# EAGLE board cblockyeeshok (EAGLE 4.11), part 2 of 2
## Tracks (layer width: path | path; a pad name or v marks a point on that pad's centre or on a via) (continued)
N$164  (via drill 0.61) (continued)
  Top 0.203: v59.05,135.89 59.05,135.25 56.52,132.72 50.8,132.72 50.16,132.08 46.35,132.08 SIDE10.6
  Bottom 0.203: v59.05,135.89 60.96,133.99 A4.B1
N$165
  Top 0.203: SIDE10.8 46.35,129.54 60.33,129.54 60.96,128.91 A4.D1
N$166
  Top 0.203: SIDE10.12 46.35,124.46 56.52,124.46 57.15,123.83 63.5,123.83 64.14,124.46 A4.E1
N$167
  Top 0.203: SIDE10.14 46.35,121.92 52.7,121.92 53.98,123.19 60.33,123.19 60.96,122.56 A4.F1
N$168
  Top 0.203: SIDE10.16 46.35,119.38 56.52,119.38 57.15,120.02 63.5,120.02 64.14,119.38 A4.H1
N$169
  Top 0.203: SIDE10.20 46.35,114.3 49.53,114.3 52.07,116.84 58.42,116.84 59.69,115.57 60.96,115.57 A4.J1
N$170  (via drill 0.61)
  Top 0.203: v50.16,113.03 56.52,113.03 57.15,113.67 63.5,113.67 64.14,113.03 A4.K1
  Bottom 0.203: v50.16,113.03 46.35,116.84 SIDE10.18
N$171
  Top 0.203: SIDE10.24 46.35,109.22 47.62,109.22 48.9,110.49 60.33,110.49 60.96,109.86 A4.L1
N$172
  Top 0.203: SIDE10.28 46.35,104.14 59.05,104.14 61.59,106.68 64.14,106.68 A4.M1
N$173
  Bottom 0.203: A4.N1 60.96,103.5 57.15,103.5 50.16,110.49 47.62,110.49 46.35,111.76 SIDE10.22
N$174
  Top 0.203: SIDE10.30 46.35,101.6 52.7,101.6 56.52,97.79 62.87,97.79 64.14,99.06 A4.P1
N$175
  Bottom 0.203: SIDE10.26 46.35,106.68 53.34,106.68 60.96,99.06 60.96,97.16 A4.R1
N$176
  Top 0.203: SIDE10.32 46.35,99.06 50.16,99.06 57.15,92.08 63.5,92.08 64.14,92.71 A4.S1
N$177
  Top 0.203: SIDE10.34 46.35,96.52 51.44,96.52 57.15,90.81 60.96,90.81 A4.T1
N$178  (via drill 0.61)
  Top 0.203: v47.62,127 46.35,128.27 45.09,128.27 44.45,128.91 44.45,132.72 45.72,133.99 SIDE10.4
  Bottom 0.203: v47.62,127 50.8,123.83 55.24,123.83 62.87,116.2 62.87,92.71 64.14,91.44 64.14,87.63 A4.U1
N$179  (via drill 0.61)
  Top 0.203: v64.14,103.5 62.23,105.41 v61.59,105.41 | v59.69,116.84 v61.59,118.75
  Bottom 0.203: v64.14,103.5 69.22,98.42 69.22,88.9 64.14,83.82 61.59,83.82 A4.V1 | v61.59,105.41 61.59,106.68 59.69,108.58 v59.69,116.84 | v61.59,118.75 61.59,119.38 66.04,123.83 66.04,125.73 61.59,130.18 53.98,130.18 46.99,137.16 46.35,137.16 SIDE10.2
N$180  (via drill 0.61)
  Top 0.203: SIDE10.33 43.18,97.16 43.18,98.42 SIDE10.31 43.18,99.69 43.18,100.97 SIDE10.29 | SIDE10.27 43.18,104.78 43.18,106.05 SIDE10.25 43.18,107.31 43.18,108.58 SIDE10.23 43.18,109.86 40.64,109.86 v37.47,106.68 | SIDE10.21 43.18,112.39 43.18,113.67 SIDE10.19 43.18,114.94 43.18,116.2 SIDE10.17 43.18,117.47 43.18,118.75 SIDE10.15 | SIDE10.3 43.18,133.99 43.18,132.72 SIDE10.5 43.18,131.44 43.18,130.18 SIDE10.7 43.18,128.91 43.18,127.64 SIDE10.9 43.18,126.36 43.18,125.09 SIDE10.11 43.18,123.83 43.18,122.56 SIDE10.13 42.55,121.92 v41.27,120.65 | v40.64,134.62 40.64,135.25 42.55,137.16 SIDE10.1 | v59.69,132.08 64.14,132.08 A4.C1 | v34.92,111.76 v34.92,119.38
  Bottom 0.203: v37.47,106.68 42.55,101.6 SIDE10.29 | v40.64,134.62 42.55,134.62 SIDE10.3 | v59.69,132.08 53.34,138.43 45.09,138.43 43.81,137.16 SIDE10.1 | v41.27,120.65 42.55,119.38 SIDE10.15 | v34.92,111.76 42.55,104.14 SIDE10.27 | v34.92,119.38 40.64,119.38 SIDE10.17
N$181  (via drill 0.61)
  Top 0.203: SIDE11.33 137.16,13.34 137.16,14.61 SIDE11.31 137.16,15.88 137.16,17.14 SIDE11.29 | SIDE11.27 137.16,20.95 137.16,22.23 SIDE11.25 137.16,23.5 137.16,24.77 SIDE11.23 137.16,26.04 137.16,27.3 SIDE11.21 | SIDE11.19 137.16,31.11 137.16,32.38 SIDE11.17 137.16,33.66 137.16,34.92 SIDE11.15 137.16,36.2 137.16,37.47 SIDE11.13 137.16,38.73 137.16,40.01 SIDE11.11 137.16,41.27 137.16,42.55 SIDE11.9 | SIDE11.5 137.16,47.62 137.16,46.35 SIDE11.7 136.53,45.72 v135.25,44.45 | v138.43,55.24 137.16,53.98 SIDE11.1
  Bottom 0.203: SIDE11.27 137.16,19.68 137.16,18.41 SIDE11.29 | SIDE11.19 137.16,29.84 137.16,28.57 SIDE11.21 | SIDE11.5 137.16,48.9 137.16,50.16 SIDE11.3 137.16,51.44 137.16,52.7 SIDE11.1 | v138.43,55.24 134.62,59.05 134.62,68.58 121.28,81.92 97.16,81.92 96.52,81.28 94.61,81.28 85.72,72.39 85.72,67.94 83.82,66.04 83.82,62.23 A6.C2 | v135.25,44.45 136.53,43.18 SIDE11.9
N$182  (via drill 0.61)
  Top 0.203: v132.08,66.04 139.7,58.42 139.7,53.98 SIDE11.2 | v111.12,78.74 109.86,77.47 105.41,77.47 v104.78,78.11 | v102.87,76.2 102.87,74.3 99.69,71.12 96.52,71.12 v95.89,71.75 | v87.63,72.39 83.82,68.58 A6.A2
  Bottom 0.203: v132.08,66.04 119.38,78.74 v111.12,78.74 | v102.87,76.2 v104.78,78.11 | v95.89,71.75 94.61,71.75 93.34,73.03 88.27,73.03 v87.63,72.39
N$183  (via drill 0.61)
  Top 0.203: v132.08,48.9 135.25,52.07 137.79,52.07 139.06,50.8 SIDE11.4 | v121.92,49.53 116.84,54.61 111.12,54.61 v108.58,52.07
  Bottom 0.203: v132.08,48.9 128.27,48.9 127.64,49.53 v121.92,49.53 | v108.58,52.07 100.97,44.45 96.52,44.45 80.64,60.33 80.64,64.14 A6.B2
N$184  (via drill 0.61)
  Top 0.203: v90.17,66.04 83.19,59.05 80.64,59.05 A6.D2 | v95.25,66.04 97.16,66.04 102.87,71.75 v109.86,71.75
  Bottom 0.203: v90.17,66.04 v95.25,66.04 | v109.86,71.75 114.94,71.75 118.75,67.94 119.38,67.94 122.56,64.77 127.64,64.77 133.35,59.05 133.35,57.78 136.53,54.61 137.79,54.61 138.43,53.98 138.43,50.16 139.7,48.9 SIDE11.6
N$185  (via drill 0.61)
  Top 0.203: v83.82,58.42 83.82,55.88 A6.E2 | v129.54,72.39 130.18,72.39 144.15,58.42 v144.15,46.99
  Bottom 0.203: v83.82,58.42 83.82,59.69 85.09,60.96 85.09,66.67 86.36,67.94 86.36,72.39 94.61,80.64 96.52,80.64 97.16,81.28 120.65,81.28 v129.54,72.39 | v144.15,46.99 142.88,45.72 140.34,45.72 SIDE11.8
N$186  (via drill 0.61)
  Top 0.203: v138.43,31.75 138.43,41.27 139.7,42.55 SIDE11.10 | v135.89,31.75 135.89,30.48 121.92,16.51 v107.95,16.51
  Bottom 0.203: v135.89,31.75 v138.43,31.75 | v107.95,16.51 105.41,16.51 100.97,12.06 97.16,12.06 87,22.23 82.55,22.23 81.92,22.86 81.92,24.13 82.55,24.77 82.55,27.94 81.28,29.21 81.28,29.84 78.74,32.38 78.74,50.16 80.01,51.44 A6.F2
N$187  (via drill 0.61)
  Top 0.203: v85.09,28.57 85.09,25.4 89.53,20.95 89.53,20.32 101.6,8.26 128.27,8.26 v128.91,7.62 | v146.69,10.16 146.69,16.51 144.15,19.05 144.15,22.23 144.78,22.86 144.78,34.92 139.7,40.01 SIDE11.12
  Bottom 0.203: v85.09,28.57 85.09,43.18 83.82,44.45 83.82,48.26 A6.H2 | v128.91,7.62 131.44,7.62 132.08,8.26 135.89,8.26 136.53,7.62 144.15,7.62 v146.69,10.16
N$188  (via drill 0.61)
  Top 0.203: v80.01,29.84 81.92,31.75 81.92,33.66 81.28,34.29 81.28,36.83 81.92,37.47 81.92,40.01 80.64,41.27 80.64,45.09 A6.J2 | v140.97,16.51 140.97,36.2 139.7,37.47 SIDE11.14
  Bottom 0.203: v80.01,29.84 81.92,27.94 81.92,24.77 81.28,24.13 81.28,21.59 81.92,20.95 81.92,14.61 93.98,2.54 120.65,2.54 134.62,16.51 v140.97,16.51
N$189  (via drill 0.61)
  Top 0.203: v78.74,13.34 78.74,27.3 82.55,31.11 82.55,33.66 81.92,34.29 81.92,36.83 83.19,38.1 83.19,41.91 A6.K2 | v134.62,5.71 142.24,13.34 v142.24,33.66
  Bottom 0.203: v78.74,13.34 90.81,1.27 130.18,1.27 v134.62,5.71 | v142.24,33.66 140.34,35.56 SIDE11.16
N$190  (via drill 0.61)
  Top 0.203: v84.45,24.77 85.09,24.13 85.09,21.59 84.45,20.95 84.45,19.05 v87,16.51 | v128.27,11.43 v135.89,11.43
  Bottom 0.203: v84.45,24.77 84.45,26.67 81.92,29.21 81.92,33.66 80.64,34.92 80.64,38.73 A6.L2 | v87,16.51 95.25,8.26 120.02,8.26 122.56,5.71 v128.27,11.43 | v135.89,11.43 140.97,11.43 146.69,17.14 146.69,25.4 139.7,32.38 SIDE11.18
N$191  (via drill 0.61)
  Top 0.203: v88.27,23.5 88.27,27.3 83.82,31.75 83.82,35.56 A6.M2 | v97.79,14.61 98.42,15.24 123.83,15.24 128.91,20.32 v135.25,20.32
  Bottom 0.203: v88.27,23.5 88.27,22.86 96.52,14.61 v97.79,14.61 | v135.25,20.32 136.53,21.59 143.51,21.59 144.78,22.86 144.78,24.77 139.7,29.84 SIDE11.20
N$192  (via drill 0.61)
  Top 0.203: v120.65,49.53 108.58,49.53 106.05,52.07 106.05,53.98 103.5,56.52 101.6,56.52 100.97,55.88 100.97,53.34 104.14,50.16 104.14,48.26 103.5,47.62 92.71,47.62 91.44,46.35 91.44,45.72 89.53,43.81 85.72,43.81 82.55,46.99 79.38,46.99 78.74,46.35 78.74,38.73 80.01,37.47 80.01,33.66 A6.N2 | v133.99,27.3 135.89,29.21 137.79,29.21 139.06,27.94 SIDE11.22
  Bottom 0.203: v120.65,49.53 123.19,46.99 128.27,46.99 128.91,47.62 130.18,47.62 131.44,46.35 131.44,43.18 130.18,41.91 130.18,31.11 v133.99,27.3
N$193  (via drill 0.61)
  Top 0.203: v83.19,20.95 81.92,22.23 81.92,24.13 83.19,25.4 83.19,29.21 A6.P2 | v120.02,6.99 v122.56,6.99
  Bottom 0.203: v83.19,20.95 83.19,19.68 85.72,17.14 85.72,16.51 87,15.24 87.63,15.24 95.89,6.99 v120.02,6.99 | v122.56,6.99 122.56,8.26 130.18,15.88 130.18,16.51 135.89,22.23 135.89,23.5 136.53,24.13 137.79,24.13 139.06,25.4 SIDE11.24
N$194  (via drill 0.61)
  Top 0.203: v143.51,22.86 143.51,16.51 145.41,14.61 v145.41,12.7 | v136.53,9.53 131.44,4.45 101.6,4.45 96.52,9.53 v90.81,9.53 | v85.09,13.34 85.09,17.78 80.64,22.23 80.64,26.04 A6.R2
  Bottom 0.203: v143.51,22.86 140.34,22.86 SIDE11.26 | v145.41,12.7 142.24,9.53 v136.53,9.53 | v90.81,9.53 88.9,9.53 v85.09,13.34
N$195  (via drill 0.61)
  Top 0.203: v138.43,26.67 138.43,22.23 139.7,20.95 SIDE11.28 | v125.09,12.06 102.23,12.06 v100.97,13.34
  Bottom 0.203: v138.43,26.67 136.53,26.67 132.08,22.23 132.08,19.05 v125.09,12.06 | v100.97,13.34 100.33,12.7 97.79,12.7 87.63,22.86 83.82,22.86 A6.S2
N$196  (via drill 0.61)
  Top 0.203: v143.51,15.24 144.15,14.61 144.15,10.16 135.25,1.27 95.89,1.27 80.64,16.51 80.64,19.68 A6.T2
  Bottom 0.203: v143.51,15.24 140.97,17.78 140.34,17.78 SIDE11.30
N$197  (via drill 0.61)
  Top 0.203: v101.6,5.71 132.08,5.71 133.35,6.99 133.35,7.62 136.53,10.79 137.16,10.79 139.06,12.7 SIDE11.34
  Bottom 0.203: v101.6,5.71 100.33,5.71 97.79,3.17 93.98,3.17 83.82,13.34 83.82,16.51 A6.U2
N$198
  Bottom 0.203: A6.V2 80.64,13.34 81.92,13.34 93.34,1.91 120.65,1.91 132.72,13.97 137.79,13.97 139.06,15.24 SIDE11.32
N$199  (via drill 0.61)
  Top 0.203: v109.22,80.01 110.49,80.01 111.12,80.64 v123.83,80.64 | v153.67,46.99 153.67,45.09 152.4,43.81 SIDE12.10
  Bottom 0.203: v109.22,80.01 99.06,69.85 95.25,69.85 93.98,71.12 91.44,68.58 90.17,68.58 A6.A1 | v123.83,80.64 149.86,54.61 150.5,54.61 151.13,53.98 151.13,52.7 151.76,52.07 153.03,52.07 153.67,51.44 v153.67,46.99
N$200  (via drill 0.61)
  Top 0.203: v122.56,73.66 123.19,73.03 125.09,73.03 125.73,73.66 133.99,73.66 153.67,53.98 153.67,50.16 152.4,48.9 SIDE12.6 | v102.23,65.41 99.69,62.87 92.71,62.87 v91.44,64.14
  Bottom 0.203: v122.56,73.66 114.94,73.66 114.3,74.3 109.86,74.3 104.14,68.58 104.14,67.31 v102.23,65.41 | v91.44,64.14 87,64.14 A6.B1
N$201  (via drill 0.61)
  Top 0.203: v90.17,57.78 91.44,57.78 v95.25,53.98 | v146.05,44.45 v148.59,46.99
  Bottom 0.203: v90.17,57.78 87,57.78 A6.D1 | v95.25,53.98 99.06,53.98 103.5,58.42 109.86,58.42 111.12,57.15 118.11,57.15 119.38,58.42 120.02,58.42 123.83,54.61 127.64,54.61 135.89,46.35 135.89,45.09 136.53,44.45 v146.05,44.45 | v148.59,46.99 150.5,46.99 151.76,45.72 SIDE12.8
N$202  (via drill 0.61)
  Top 0.203: v154.31,43.18 152.4,41.27 SIDE12.12 | v132.08,62.87 v135.89,59.05 | v129.54,65.41 129.54,68.58 127.64,70.48 102.23,70.48 v95.89,64.14 | v91.44,61.59 91.44,60.96 90.81,60.33 90.17,60.33 88.9,59.05 88.9,56.52 89.53,55.88 A6.E1
  Bottom 0.203: v154.31,43.18 153.03,44.45 149.22,44.45 140.97,52.7 140.97,53.98 v135.89,59.05 | v129.54,65.41 v132.08,62.87 | v95.89,64.14 93.34,61.59 v91.44,61.59
N$203  (via drill 0.61)
  Top 0.203: v89.53,45.09 88.9,44.45 85.72,44.45 85.09,45.09 85.09,46.35 86.36,47.62 86.36,51.44 A6.F1 | v129.54,25.4 134.62,30.48 v134.62,34.92 | v147.96,34.29 v147.96,38.1
  Bottom 0.203: v89.53,45.09 91.44,43.18 91.44,34.29 86.36,29.21 86.36,28.57 85.09,27.3 85.09,26.04 85.72,25.4 91.44,25.4 98.42,18.41 104.78,18.41 105.41,17.78 106.68,19.05 111.12,19.05 117.47,25.4 127,25.4 127.64,26.04 128.91,26.04 v129.54,25.4 | v134.62,34.92 136.53,36.83 145.41,36.83 v147.96,34.29 | v147.96,38.1 149.22,39.37 150.5,39.37 151.76,38.1 SIDE12.14
N$204  (via drill 0.61)
  Top 0.203: v133.35,36.2 133.35,30.48 v127.64,24.77 | v91.44,24.13 88.9,26.67 88.9,27.94 v86.36,30.48
  Bottom 0.203: v133.35,36.2 136.53,39.37 144.78,39.37 147.32,36.83 150.5,36.83 151.76,35.56 SIDE12.16 | v127.64,24.77 126.36,24.77 125.73,24.13 116.84,24.13 110.49,17.78 106.05,17.78 104.14,15.88 99.69,15.88 v91.44,24.13 | v86.36,30.48 88.27,32.38 88.27,46.99 89.53,48.26 A6.H1
N$205  (via drill 0.61)
  Top 0.203: v89.53,52.7 87,50.16 87,46.35 A6.J1 | v142.88,46.99 142.88,41.27 146.69,37.47 v146.69,34.29
  Bottom 0.203: v89.53,52.7 91.44,54.61 91.44,59.05 92.08,59.69 102.87,59.69 106.68,63.5 106.68,67.31 110.49,71.12 114.94,71.12 118.75,67.31 119.38,67.31 121.28,65.41 121.28,62.23 123.83,59.69 127.64,59.69 129.54,57.78 129.54,53.98 136.53,46.99 v142.88,46.99 | v146.69,34.29 149.22,31.75 150.5,31.75 151.76,30.48 SIDE12.20
N$206  (via drill 0.61)
  Top 0.203: v144.15,38.1 140.97,41.27 140.97,43.81 140.34,44.45 136.53,44.45 133.35,41.27 133.35,37.47 127.64,31.75 126.36,31.75 125.73,31.11 125.73,27.3 120.65,22.23 111.76,22.23 111.12,21.59 v109.22,21.59 | v97.16,28.57 88.9,28.57 88.27,29.21 88.27,40.64 89.53,41.91 A6.K1
  Bottom 0.203: v144.15,38.1 145.41,38.1 149.22,34.29 150.5,34.29 151.76,33.02 SIDE12.18 | v109.22,21.59 102.23,21.59 97.16,26.67 v97.16,28.57
N$207  (via drill 0.61)
  Top 0.203: v75.56,60.96 75.56,59.69 76.2,59.05 76.2,57.15 74.93,55.88 74.93,53.34 75.56,52.7 75.56,51.44 74.93,50.8 71.12,50.8 v67.94,53.98 | v60.33,55.24 54.61,60.96 v50.16,60.96 | v50.16,67.94 54.61,67.94 v55.88,69.22 | v49.53,81.28 32.38,81.28 v29.21,78.11 | v6.35,56.52 6.35,78.11 1.91,82.55 1.91,123.83 27.94,149.86 126.36,149.86 156.21,120.02 156.21,29.84 152.4,26.04 SIDE12.24
  Bottom 0.203: v75.56,60.96 85.09,51.44 85.09,45.09 86.36,43.81 86.36,40.01 A6.L1 | v67.94,53.98 61.59,53.98 v60.33,55.24 | v50.16,67.94 v50.16,60.96 | v55.88,69.22 49.53,75.56 v49.53,81.28 | v29.21,78.11 29.21,77.47 8.26,56.52 v6.35,56.52
N$208  (via drill 0.61)
  Top 0.203: v94.61,35.56 90.17,35.56 A6.M1 | v106.05,20.32 107.31,21.59 109.22,19.68 114.3,19.68 v114.94,20.32 | v129.54,22.86 130.81,22.86 v135.25,27.3
  Bottom 0.203: v94.61,35.56 94.61,28.57 102.87,20.32 v106.05,20.32 | v114.94,20.32 118.11,23.5 128.91,23.5 v129.54,22.86 | v135.25,27.3 134.62,27.94 134.62,32.38 136.53,34.29 140.34,34.29 148.59,26.04 148.59,22.23 149.22,21.59 150.5,21.59 151.76,20.32 SIDE12.28
N$209  (via drill 0.61)
  Top 0.203: v82.55,45.72 85.09,43.18 85.09,38.73 86.36,37.47 86.36,33.66 A6.N1 | v80.01,48.26 v87,55.24 | v111.12,77.47 v128.27,77.47 | v154.94,31.11 152.4,28.57 SIDE12.22
  Bottom 0.203: v82.55,45.72 v80.01,48.26 | v87,55.24 85.09,57.15 85.09,59.05 88.9,62.87 93.34,62.87 107.95,77.47 v111.12,77.47 | v128.27,77.47 151.13,54.61 153.03,54.61 155.57,52.07 155.57,31.75 v154.94,31.11
N$210  (via drill 0.61)
  Top 0.203: v132.72,41.91 127.64,36.83 v125.73,36.83 | v106.68,31.75 100.97,31.75 100.33,31.11 90.81,31.11 90.17,30.48 A6.P1
  Bottom 0.203: v132.72,41.91 153.03,41.91 153.67,41.27 153.67,19.68 152.4,18.41 SIDE12.30 | v125.73,36.83 120.65,36.83 115.57,31.75 v106.68,31.75
N$211  (via drill 0.61)
  Top 0.203: v105.41,19.05 107.95,19.05 108.58,18.41 118.75,18.41 v119.38,19.05 | v124.46,13.97 128.27,10.16 128.91,10.16 v132.08,6.99 | v148.59,6.99 153.67,12.06 153.67,20.95 152.4,22.23 SIDE12.26
  Bottom 0.203: v105.41,19.05 98.42,19.05 91.44,26.04 87,26.04 A6.R1 | v119.38,19.05 v124.46,13.97 | v132.08,6.99 v148.59,6.99
N$212  (via drill 0.61)
  Top 0.203: v128.91,8.89 104.78,8.89 101.6,12.06 98.42,12.06 90.17,20.32 90.17,22.86 A6.S1
  Bottom 0.203: v128.91,8.89 135.89,8.89 136.53,8.26 143.51,8.26 149.22,13.97 150.5,13.97 151.76,15.24 SIDE12.32
N$213  (via drill 0.61)
  Top 0.203: v142.88,11.43 142.88,9.53 135.25,1.91 97.16,1.91 88.27,10.79 88.27,18.41 87,19.68 A6.T1
  Bottom 0.203: v142.88,11.43 147.96,16.51 153.03,16.51 153.67,15.88 153.67,14.61 152.4,13.34 SIDE12.34
N$214  (via drill 0.61)
  Top 0.203: v97.16,10.16 94.61,10.16 90.17,14.61 90.17,16.51 A6.U1 | v130.18,46.35 130.18,48.26 138.43,56.52 v138.43,57.78
  Bottom 0.203: v97.16,10.16 121.92,10.16 131.44,19.68 131.44,28.57 129.54,30.48 129.54,45.72 v130.18,46.35 | v138.43,57.78 143.51,57.78 149.22,52.07 150.5,52.07 151.76,50.8 SIDE12.4
N$215  (via drill 0.61)
  Top 0.203: v97.79,4.45 100.97,4.45 102.87,2.54 134.62,2.54 v137.79,5.71 | v144.78,5.71 151.13,12.06 151.13,51.44 152.4,52.7 SIDE12.2
  Bottom 0.203: v97.79,4.45 88.9,13.34 87,13.34 A6.V1 | v137.79,5.71 v144.78,5.71
N$216  (via drill 0.61)
  Top 0.203: SIDE12.33 149.86,13.34 149.86,14.61 SIDE12.31 149.86,15.88 149.86,17.14 SIDE12.29 149.86,18.41 149.86,19.68 SIDE12.27 149.86,20.95 149.86,22.23 SIDE12.25 149.86,23.5 149.86,24.77 SIDE12.23 149.86,26.04 149.86,27.3 SIDE12.21 149.86,28.57 149.86,29.84 SIDE12.19 149.86,31.11 149.86,32.38 SIDE12.17 149.86,33.66 149.86,34.92 SIDE12.15 149.86,36.2 149.86,37.47 SIDE12.13 149.86,38.73 149.86,40.01 SIDE12.11 149.86,41.27 149.86,42.55 SIDE12.9 149.86,43.81 149.86,45.09 SIDE12.7 149.86,46.35 149.86,47.62 SIDE12.5 149.86,48.9 149.86,50.16 SIDE12.3 149.86,51.44 149.86,52.7 SIDE12.1 | v106.68,73.03 121.92,73.03 122.56,72.39 127.64,72.39 v138.43,61.59
  Bottom 0.203: v106.68,73.03 104.78,73.03 97.79,66.04 97.79,64.77 95.89,62.87 95.25,62.87 92.71,60.33 91.44,60.33 90.81,60.96 90.17,60.96 A6.C1 | v138.43,61.59 140.97,61.59 149.22,53.34 SIDE12.1
N$217  (via drill 0.61)
  Top 0.203: SIDE13.33 5.08,13.34 5.08,14.61 SIDE13.31 5.08,15.88 5.08,17.14 SIDE13.29 5.08,18.41 5.08,19.68 SIDE13.27 5.08,20.95 5.08,22.23 SIDE13.25 5.08,23.5 5.08,24.77 SIDE13.23 5.08,26.04 5.08,27.3 SIDE13.21 5.08,28.57 5.08,29.84 SIDE13.19 5.08,31.11 5.08,32.38 SIDE13.17 5.08,33.66 5.08,34.92 SIDE13.15 5.08,36.2 5.08,37.47 SIDE13.13 5.08,38.73 5.08,40.01 SIDE13.11 5.08,41.27 5.08,42.55 SIDE13.9 5.08,43.81 5.08,45.09 SIDE13.7 5.08,46.35 5.08,47.62 SIDE13.5 5.08,48.9 5.08,50.16 SIDE13.3 5.08,51.44 5.08,52.7 SIDE13.1 | v62.23,63.5 62.23,61.59 66.67,57.15 74.93,57.15 75.56,57.78 75.56,59.05 73.66,60.96 71.12,60.96 A7.C2 | v30.48,78.11 v45.09,78.11
  Bottom 0.203: v62.23,63.5 59.69,63.5 v45.09,78.11 | v30.48,78.11 5.71,53.34 SIDE13.1
N$218  (via drill 0.61)
  Top 0.203: v54.61,74.3 53.98,73.66 22.86,73.66 13.34,83.19 11.43,83.19 7.62,79.38 7.62,53.98 SIDE13.2
  Bottom 0.203: v54.61,74.3 57.78,71.12 67.94,71.12 70.48,68.58 A7.A2
N$219  (via drill 0.61)
  Top 0.203: v59.05,9.53 18.41,9.53 15.88,12.06 15.88,15.24 9.53,21.59 9.53,23.5 8.89,24.13 8.89,48.9 7.62,50.16 SIDE13.4 | v66.04,17.14 67.94,19.05 68.58,19.05 72.39,22.86 72.39,38.1 v68.58,41.91 | v69.22,61.59 69.22,62.87 67.94,64.14 A7.B2
  Bottom 0.203: v59.05,9.53 66.04,16.51 v66.04,17.14 | v68.58,41.91 65.41,45.09 65.41,46.99 66.67,48.26 67.31,48.26 69.22,50.16 v69.22,61.59
N$220  (via drill 0.61)
  Top 0.203: v29.21,64.77 29.21,69.22 29.84,69.85 46.35,69.85 50.16,66.04 62.23,66.04 67.31,60.96 67.31,59.05 A7.D2
  Bottom 0.203: v29.21,64.77 28.57,64.14 22.86,64.14 7.62,48.9 SIDE13.6
N$221  (via drill 0.61)
  Top 0.203: v10.16,45.72 10.16,21.59 16.51,15.24 16.51,12.06 17.78,10.79 v62.23,10.79 | v73.66,24.77 74.3,24.77 75.56,26.04 75.56,41.27 73.66,43.18 75.56,45.09 v75.56,48.26
  Bottom 0.203: v10.16,45.72 8.26,45.72 SIDE13.8 | v62.23,10.79 67.31,15.88 71.75,15.88 75.56,19.68 75.56,22.23 73.66,24.13 v73.66,24.77 | v75.56,48.26 71.12,52.7 71.12,54.61 A7.E2
N$222  (via drill 0.61)
  Top 0.203: v19.05,44.45 v27.3,44.45 | v38.73,46.99 40.01,46.99 42.55,44.45 62.23,44.45 v67.31,49.53
  Bottom 0.203: v19.05,44.45 17.14,44.45 15.88,43.18 8.26,43.18 SIDE13.10 | v27.3,44.45 29.84,46.99 v38.73,46.99 | v67.31,49.53 67.31,51.44 A7.F2
N$223  (via drill 0.61)
  Top 0.203: v6.35,52.07 6.35,42.55 7.62,41.27 SIDE13.12 | v60.96,62.23 66.67,56.52 66.67,53.34 66.04,52.7 66.04,51.44 66.67,50.8 69.22,50.8 70.48,49.53 A7.H2
  Bottom 0.203: v6.35,52.07 8.89,52.07 27.94,71.12 49.53,71.12 54.61,66.04 56.52,66.04 60.33,62.23 v60.96,62.23
N$224  (via drill 0.61)
  Top 0.203: v52.7,34.29 60.96,34.29 v62.87,36.2 | v66.04,41.91 66.04,43.81 67.31,45.09 A7.J2
  Bottom 0.203: v52.7,34.29 42.55,34.29 34.92,41.91 29.84,41.91 22.23,34.29 14.61,34.29 10.79,38.1 8.26,38.1 SIDE13.14 | v62.87,36.2 62.87,38.73 v66.04,41.91
N$225  (via drill 0.61)
  Top 0.203: v15.88,2.54 6.35,12.06 6.35,33.66 7.62,34.92 SIDE13.16 | v74.3,35.56 74.3,36.83 71.12,40.01 71.12,41.91 A7.K2
  Bottom 0.203: v15.88,2.54 30.48,2.54 31.75,1.27 63.5,1.27 78.74,16.51 78.74,24.77 78.11,25.4 78.11,28.57 78.74,29.21 78.74,31.11 v74.3,35.56
N$226  (via drill 0.61)
  Top 0.203: v35.56,31.75 37.47,31.75 42.55,26.67 43.81,26.67 44.45,27.3 44.45,36.2 45.09,36.83 55.88,36.83 57.15,38.1 v64.77,38.1
  Bottom 0.203: v35.56,31.75 17.14,31.75 15.88,33.02 8.26,33.02 SIDE13.18 | v64.77,38.1 66.67,38.1 67.31,38.73 A7.L2
N$227  (via drill 0.61)
  Top 0.203: v11.43,30.48 v11.43,38.73 | v19.05,36.83 20.95,36.83 29.21,28.57 29.21,27.3 31.11,25.4 38.73,25.4 40.64,27.3 41.27,27.3 42.55,26.04 v48.9,26.04 | v56.52,26.04 59.69,26.04 60.33,25.4 63.5,25.4 v64.77,26.67
  Bottom 0.203: v11.43,30.48 8.26,30.48 SIDE13.20 | v11.43,38.73 15.24,38.73 17.14,36.83 v19.05,36.83 | v48.9,26.04 50.8,24.13 51.44,24.13 52.7,25.4 55.88,25.4 v56.52,26.04 | v64.77,26.67 73.03,34.92 73.03,35.56 75.56,38.1 75.56,40.01 74.93,40.64 73.03,40.64 71.12,38.73 71.12,36.83 A7.M2
N$228  (via drill 0.61)
  Top 0.203: v26.04,77.47 33.66,85.09 57.78,85.09 v59.05,83.82 | v78.74,68.58 78.74,46.99 v74.93,43.18
  Bottom 0.203: v26.04,77.47 3.81,55.24 3.81,29.84 4.45,29.21 5.71,29.21 6.99,27.94 SIDE13.22 | v59.05,83.82 60.96,81.92 65.41,81.92 v78.74,68.58 | v74.93,43.18 67.94,36.2 67.94,33.66 A7.N2
N$229  (via drill 0.61)
  Top 0.203: v53.34,8.26 19.05,8.26 15.24,12.06 15.24,15.24 8.89,21.59 8.89,23.5 7.62,24.77 SIDE13.24 | v62.87,17.14 62.87,18.41 70.48,26.04 70.48,29.21 A7.P2
  Bottom 0.203: v53.34,8.26 62.23,17.14 v62.87,17.14
N$230  (via drill 0.61)
  Top 0.203: v61.59,9.53 59.05,6.99 19.68,6.99 12.7,13.97 12.7,17.14 7.62,22.23 SIDE13.26 | v65.41,9.53 67.31,9.53 71.75,13.97 71.75,15.88 75.56,19.68 v75.56,23.5
  Bottom 0.203: v61.59,9.53 v65.41,9.53 | v75.56,23.5 75.56,33.66 74.93,34.29 73.03,34.29 67.94,29.21 67.94,27.3 A7.R2
N$231
  Bottom 0.203: SIDE13.28 8.26,20.32 10.79,20.32 17.14,26.67 36.2,26.67 37.47,27.94 40.01,27.94 48.9,19.05 57.78,19.05 60.96,22.23 69.85,22.23 70.48,22.86 A7.S2
N$232  (via drill 0.61)
  Top 0.203: v71.75,19.68 71.12,19.68 66.04,14.61 66.04,12.7 58.42,5.08 20.95,5.08 8.26,17.78 SIDE13.30
  Bottom 0.203: v71.75,19.68 67.94,19.68 A7.T2
N$233  (via drill 0.61)
  Top 0.203: v67.94,11.43 70.48,13.97 70.48,16.51 A7.U2
  Bottom 0.203: v67.94,11.43 67.94,10.79 60.96,3.81 60.33,4.45 23.5,4.45 15.24,12.7 8.26,12.7 SIDE13.34
N$234
  Top 0.203: SIDE13.32 8.26,15.24 10.16,15.24 24.13,1.27 55.24,1.27 67.31,13.34 A7.V2
N$235  (via drill 0.61)
  Top 0.203: v21.59,61.59 v21.59,66.04 | v30.48,76.2 31.75,77.47 44.45,77.47 45.09,76.83 47.62,76.83 50.16,79.38 v53.98,79.38
  Bottom 0.203: v21.59,61.59 21.59,45.09 20.32,43.81 SIDE14.10 | v21.59,66.04 21.59,67.31 v30.48,76.2 | v53.98,79.38 55.88,79.38 57.78,81.28 64.14,81.28 76.83,68.58 A7.A1
N$236  (via drill 0.61)
  Top 0.203: v49.53,69.22 47.62,71.12 29.84,71.12 27.3,68.58 27.3,54.61 20.95,48.26 SIDE14.6 | v51.44,59.69 v54.61,56.52 | v69.85,63.5 73.03,63.5 73.66,64.14 A7.B1
  Bottom 0.203: v49.53,69.22 50.16,69.22 51.44,67.94 v51.44,59.69 | v54.61,56.52 62.87,56.52 v69.85,63.5
N$237
  Top 0.203: SIDE14.8 20.32,46.35 27.94,53.98 27.94,68.58 29.84,70.48 46.35,70.48 50.16,66.67 62.87,66.67 70.48,59.05 73.66,59.05 A7.D1
N$238  (via drill 0.61)
  Top 0.203: v22.86,62.87 26.04,66.04 26.04,68.58 30.48,73.03 v54.61,73.03
  Bottom 0.203: v22.86,62.87 22.86,43.81 20.32,41.27 SIDE14.12 | v54.61,73.03 57.15,70.48 64.77,70.48 76.83,58.42 76.83,55.88 A7.E1
N$239  (via drill 0.61)
  Top 0.203: v36.2,54.61 40.01,54.61 42.55,57.15 43.81,57.15 44.45,56.52 44.45,52.7 45.09,52.07 52.7,52.07 53.98,50.8 62.23,50.8 66.04,54.61 66.04,55.88 v65.41,56.52 | v67.94,55.88 71.12,52.7 73.66,52.7 A7.F1
  Bottom 0.203: v36.2,54.61 24.77,54.61 23.5,53.34 23.5,41.91 20.32,38.73 SIDE14.14 | v65.41,56.52 67.31,56.52 v67.94,55.88
N$240  (via drill 0.61)
  Top 0.203: v24.77,53.34 24.77,60.96 26.67,62.87 26.67,68.58 29.84,71.75 48.9,71.75 50.16,70.48 56.52,70.48 57.15,71.12 58.42,71.12 60.33,69.22 v63.5,69.22
  Bottom 0.203: v24.77,53.34 24.77,40.64 20.32,36.2 SIDE14.16 | v63.5,69.22 65.41,69.22 75.56,59.05 75.56,50.8 76.83,49.53 A7.H1
N$241  (via drill 0.61)
  Top 0.203: v50.16,26.04 48.9,24.77 43.18,24.77 41.27,26.67 40.64,26.67 38.73,24.77 31.11,24.77 25.4,30.48 20.95,30.48 SIDE14.20 | v52.07,27.94 52.7,27.94 53.34,28.57 60.33,28.57 v61.59,29.84
  Bottom 0.203: v50.16,26.04 v52.07,27.94 | v61.59,29.84 61.59,31.11 73.66,43.18 73.66,45.09 A7.J1
N$242  (via drill 0.61)
  Top 0.203: v31.75,39.37 40.01,39.37 42.55,41.91 46.35,41.91 48.26,43.81 63.5,43.81 v66.67,46.99
  Bottom 0.203: v31.75,39.37 29.84,39.37 23.5,33.02 20.95,33.02 SIDE14.18 | v66.67,46.99 74.93,46.99 76.83,45.09 76.83,43.18 A7.K1
N$243  (via drill 0.61)
  Top 0.203: v40.64,25.4 41.91,25.4 43.18,24.13 50.16,24.13 v51.44,25.4 | v53.34,27.3 53.98,27.94 v64.77,27.94
  Bottom 0.203: v40.64,25.4 20.95,25.4 SIDE14.24 | v51.44,25.4 v53.34,27.3 | v64.77,27.94 73.66,36.83 73.66,38.73 A7.L1
N$244  (via drill 0.61)
  Top 0.203: v51.44,15.24 56.52,15.24 59.69,12.06 62.87,12.06 78.74,27.94 78.74,34.29 77.47,35.56 A7.M1
  Bottom 0.203: v51.44,15.24 46.35,20.32 20.95,20.32 SIDE14.28
N$245  (via drill 0.61)
  Top 0.203: v52.7,24.13 52.07,23.5 31.75,23.5 27.3,27.94 20.95,27.94 SIDE14.22
  Bottom 0.203: v52.7,24.13 55.88,24.13 57.15,25.4 68.58,25.4 73.66,30.48 73.66,32.38 A7.N1
N$246  (via drill 0.61)
  Top 0.203: v46.35,17.78 54.61,17.78 59.69,12.7 62.87,12.7 76.83,26.67 76.83,29.21 A7.P1
  Bottom 0.203: v46.35,17.78 20.95,17.78 SIDE14.30
N$247  (via drill 0.61)
  Top 0.203: v53.98,22.86 20.95,22.86 SIDE14.26
  Bottom 0.203: v53.98,22.86 55.24,22.86 57.15,24.77 72.39,24.77 73.66,26.04 A7.R1
N$248  (via drill 0.61)
  Top 0.203: v62.23,6.99 v66.04,6.99 | v76.83,19.05 76.83,22.86 A7.S1
  Bottom 0.203: v62.23,6.99 33.66,6.99 25.4,15.24 20.95,15.24 SIDE14.32 | v66.04,6.99 72.39,13.34 72.39,14.61 v76.83,19.05
N$249  (via drill 0.61)
  Top 0.203: v59.05,18.41 55.88,21.59 29.84,21.59 20.95,12.7 SIDE14.34
  Bottom 0.203: v59.05,18.41 72.39,18.41 73.66,19.68 A7.T1
N$250  (via drill 0.61)
  Top 0.203: v13.34,45.72 13.34,38.1 15.24,36.2 v15.24,17.78 | v64.14,8.26 66.67,8.26 72.39,13.97 72.39,14.61 74.3,16.51 76.83,16.51 A7.U1
  Bottom 0.203: v13.34,45.72 17.14,49.53 18.41,49.53 19.68,50.8 SIDE14.4 | v15.24,17.78 15.24,13.34 23.5,5.08 60.33,5.08 60.96,4.45 64.14,7.62 v64.14,8.26
N$251  (via drill 0.61)
  Top 0.203: v59.05,2.54 65.41,2.54 73.66,10.79 73.66,13.34 A7.V1
  Bottom 0.203: v59.05,2.54 31.11,2.54 29.84,3.81 14.61,3.81 6.35,12.06 6.35,20.95 6.99,21.59 8.26,21.59 8.89,22.23 8.89,28.57 8.26,29.21 6.99,29.21 6.35,29.84 6.35,43.81 6.99,44.45 10.16,44.45 11.43,45.72 11.43,46.35 17.14,52.07 18.41,52.07 19.68,53.34 SIDE14.2
N$252
  Top 0.203: SIDE14.1 17.78,52.7 17.78,51.44 SIDE14.3 17.78,50.16 17.78,48.9 SIDE14.5 17.78,47.62 17.78,46.35 SIDE14.7 17.78,45.09 17.78,43.81 SIDE14.9 17.78,42.55 17.78,41.27 SIDE14.11 17.78,40.01 17.78,38.73 SIDE14.13 17.78,37.47 17.78,36.2 SIDE14.15 17.78,34.92 17.78,33.66 SIDE14.17 17.78,32.38 17.78,31.11 SIDE14.19 17.78,29.84 17.78,28.57 SIDE14.21 17.78,27.3 17.78,26.04 SIDE14.23 17.78,24.77 17.78,23.5 SIDE14.25 17.78,22.23 17.78,20.95 SIDE14.27 17.78,19.68 17.78,18.41 SIDE14.29 17.78,17.14 17.78,15.88 SIDE14.31 17.78,14.61 17.78,13.34 SIDE14.33 18.41,12.7 19.68,11.43 20.95,11.43 28.57,19.05 53.98,19.05 57.15,15.88 59.05,15.88 66.04,22.86 66.04,40.64 76.2,50.8 76.2,53.34 75.56,53.98 75.56,55.88 76.83,57.15 76.83,60.96 A7.C1
N$253  (via drill 0.61)
  Top 0.203: SIDE15.33 30.48,28.57 30.48,29.84 SIDE15.31 30.48,31.11 30.48,32.38 SIDE15.29 30.48,33.66 30.48,34.92 SIDE15.27 30.48,36.2 30.48,37.47 SIDE15.25 30.48,38.73 30.48,40.01 SIDE15.23 30.48,41.27 30.48,42.55 SIDE15.21 30.48,43.81 30.48,45.09 SIDE15.19 30.48,46.35 30.48,47.62 SIDE15.17 30.48,48.9 30.48,50.16 SIDE15.15 30.48,51.44 30.48,52.7 SIDE15.13 30.48,53.98 30.48,55.24 SIDE15.11 30.48,56.52 30.48,57.78 SIDE15.9 30.48,59.05 30.48,60.33 SIDE15.7 30.48,61.59 30.48,62.87 SIDE15.5 30.48,64.14 30.48,65.41 SIDE15.3 30.48,66.67 30.48,67.94 SIDE15.1 | v48.26,61.59 48.9,62.23 57.78,62.23 A8.C2
  Bottom 0.203: v48.26,61.59 46.99,61.59 46.35,62.23 36.2,62.23 33.66,64.77 32.38,64.77 31.11,66.04 SIDE15.3
N$254  (via drill 0.61)
  Top 0.203: v24.77,66.67 v24.77,69.22 | v31.75,76.2 v48.26,76.2
  Bottom 0.203: v24.77,66.67 27.94,69.85 31.11,69.85 32.38,68.58 SIDE15.2 | v24.77,69.22 v31.75,76.2 | v48.26,76.2 54.61,69.85 54.61,69.22 55.88,67.94 57.78,67.94 A8.A2
N$255
  Bottom 0.203: A8.B2 54.61,65.41 49.53,70.48 38.73,70.48 34.29,66.04 33.66,66.04 SIDE15.4
N$256
  Bottom 0.203: SIDE15.6 33.66,63.5 42.55,54.61 48.9,54.61 51.44,57.15 53.98,57.15 54.61,57.78 A8.D2
N$257  (via drill 0.61)
  Top 0.203: v41.27,60.96 33.66,60.96 SIDE15.8 | v50.16,59.69 54.61,55.24 57.78,55.24 A8.E2
  Bottom 0.203: v41.27,60.96 42.55,59.69 v50.16,59.69
N$258
  Bottom 0.203: SIDE15.10 33.66,58.42 36.2,58.42 42.55,52.07 54.61,52.07 A8.F2
N$259
  Bottom 0.203: SIDE15.12 33.66,55.88 36.2,55.88 42.55,49.53 57.78,49.53 A8.H2
N$260
  Bottom 0.203: SIDE15.14 33.66,53.34 36.2,53.34 42.55,46.99 53.98,46.99 54.61,46.35 A8.J2
N$261  (via drill 0.61)
  Top 0.203: v41.27,43.18 40.01,43.18 33.02,50.16 SIDE15.16 | v47.62,41.91 57.78,41.91 A8.K2
  Bottom 0.203: v41.27,43.18 42.55,41.91 v47.62,41.91
N$262
  Bottom 0.203: SIDE15.18 33.66,48.26 38.73,48.26 42.55,44.45 50.16,44.45 54.61,40.01 A8.L2
N$263  (via drill 0.61)
  Top 0.203: v50.16,39.37 v52.7,39.37
  Bottom 0.203: v50.16,39.37 42.55,39.37 36.2,45.72 33.66,45.72 SIDE15.20 | v52.7,39.37 55.24,36.83 57.78,36.83 A8.M2
N$264
  Bottom 0.203: SIDE15.22 33.66,43.18 36.2,43.18 42.55,36.83 51.44,36.83 54.61,33.66 A8.N2
N$265
  Bottom 0.203: SIDE15.24 33.66,40.64 42.55,31.75 56.52,31.75 57.78,30.48 A8.P2
N$266
  Bottom 0.203: A8.R2 54.61,27.3 52.7,29.21 42.55,29.21 33.66,38.1 SIDE15.26
N$267
  Bottom 0.203: SIDE15.28 33.66,35.56 47.62,21.59 56.52,21.59 57.78,22.86 A8.S2
N$268
  Bottom 0.203: SIDE15.30 33.66,33.02 35.56,33.02 47.62,20.95 54.61,20.95 A8.T2
N$269  (via drill 0.61)
  Top 0.203: v19.05,16.51 v19.05,29.21
  Bottom 0.203: v19.05,16.51 24.77,16.51 29.21,12.06 55.88,12.06 57.78,13.97 57.78,16.51 A8.U2 | v19.05,29.21 31.11,29.21 32.38,27.94 SIDE15.34
N$270  (via drill 0.61)
  Top 0.203: v37.47,26.67 33.66,30.48 SIDE15.32
  Bottom 0.203: v37.47,26.67 40.64,26.67 50.8,16.51 52.7,16.51 54.61,14.61 A8.V2
N$271  (via drill 0.61)
  Top 0.203: v58.42,58.42 58.42,59.69 v59.69,60.96
  Bottom 0.203: v58.42,58.42 56.52,60.33 53.98,60.33 52.07,58.42 46.35,58.42 SIDE16.10 | v59.69,60.96 60.96,60.96 64.14,64.14 64.14,67.31 A8.A1
N$272
  Top 0.203: SIDE16.6 46.35,63.5 60.33,63.5 60.96,64.14 A8.B1
N$273
  Top 0.203: SIDE16.8 46.35,60.96 48.26,62.87 59.05,62.87 60.96,60.96 60.96,59.05 A8.D1
N$274
  Top 0.203: SIDE16.12 46.35,55.88 48.9,55.88 50.8,53.98 63.5,53.98 64.14,54.61 A8.E1
N$275
  Top 0.203: SIDE16.14 46.35,53.34 60.33,53.34 60.96,52.7 A8.F1
N$276
  Top 0.203: SIDE16.16 46.35,50.8 53.34,50.8 53.98,50.16 63.5,50.16 64.14,49.53 A8.H1
N$277
  Top 0.203: SIDE16.20 46.35,45.72 52.7,45.72 53.98,46.99 60.33,46.99 60.96,46.35 A8.J1
N$278
  Bottom 0.203: SIDE16.18 46.35,48.26 56.52,48.26 61.59,43.18 64.14,43.18 A8.K1
N$279
  Top 0.203: SIDE16.24 46.35,40.64 60.33,40.64 60.96,40.01 A8.L1
N$280
  Top 0.203: SIDE16.28 46.35,35.56 55.24,35.56 57.15,37.47 63.5,37.47 64.14,36.83 A8.M1
N$281
  Bottom 0.203: SIDE16.22 46.35,43.18 47.62,43.18 57.15,33.66 60.96,33.66 A8.N1
N$282
  Top 0.203: SIDE16.30 46.35,33.02 52.7,33.02 54.61,31.11 63.5,31.11 64.14,30.48 A8.P1
N$283
  Bottom 0.203: SIDE16.26 46.35,38.1 52.07,38.1 60.96,29.21 60.96,27.3 A8.R1
N$284
  Top 0.203: SIDE16.32 46.35,30.48 48.26,30.48 53.98,24.77 63.5,24.77 64.14,24.13 A8.S1
N$285
  Top 0.203: SIDE16.34 46.35,27.94 50.16,27.94 57.15,20.95 60.96,20.95 A8.T1
N$286  (via drill 0.61)
  Top 0.203: v36.2,64.77 33.66,62.23 v31.75,62.23 | v24.77,62.23 16.51,53.98 v16.51,19.05 | v65.41,19.68 65.41,18.41 64.77,17.78 A8.U1
  Bottom 0.203: v36.2,64.77 43.81,64.77 45.09,66.04 SIDE16.4 | v24.77,62.23 v31.75,62.23 | v16.51,19.05 46.35,19.05 52.7,12.7 55.88,12.7 56.52,13.34 56.52,17.78 57.15,18.41 57.78,18.41 59.05,19.68 59.69,19.68 60.33,19.05 64.77,19.05 v65.41,19.68
N$287  (via drill 0.61)
  Top 0.203: v69.22,40.01 69.22,25.4 61.59,17.78 61.59,14.61 A8.V1 | v50.8,55.24 46.35,59.69 45.09,59.69 44.45,60.33 44.45,66.67 45.72,67.94 SIDE16.2
  Bottom 0.203: v69.22,40.01 53.98,55.24 v50.8,55.24
N$288
  Top 0.203: SIDE16.33 43.18,28.57 43.18,29.84 SIDE16.31 43.18,31.11 43.18,32.38 SIDE16.29 43.18,33.66 43.18,34.92 SIDE16.27 43.18,36.2 43.18,37.47 SIDE16.25 43.18,38.73 43.18,40.01 SIDE16.23 | SIDE16.19 43.18,46.35 43.18,47.62 SIDE16.17 43.18,48.9 43.18,50.16 SIDE16.15 43.18,51.44 43.18,52.7 | 43.18,52.7 SIDE16.13 | SIDE16.11 43.18,55.24 43.18,53.98 SIDE16.13 | SIDE16.9 43.18,59.05 43.18,60.33 SIDE16.7 43.18,61.59 43.18,62.87 SIDE16.5 43.18,64.14 43.18,65.41 SIDE16.3 43.18,66.67 43.18,67.94 SIDE16.1 | 43.18,52.7 37.47,46.99 38.73,45.72 40.01,45.72 42.55,43.18 SIDE16.21 | 43.18,52.7 SIDE16.13
  Bottom 0.203: SIDE16.21 42.55,43.18 41.27,44.45 40.01,43.18 42.55,40.64 SIDE16.23 | 43.18,57.15 43.18,56.52 SIDE16.11 | 43.18,57.15 43.18,57.78 SIDE16.9 | 43.18,57.15 46.35,57.15 46.99,57.78 52.07,57.78 53.98,59.69 55.88,59.69 58.42,57.15 62.23,57.15 64.14,59.05 64.14,60.96 A8.C1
